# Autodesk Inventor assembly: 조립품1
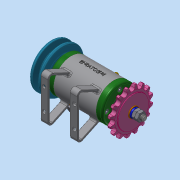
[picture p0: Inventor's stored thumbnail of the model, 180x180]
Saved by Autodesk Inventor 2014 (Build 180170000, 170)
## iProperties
Created: 2021-12
Part Number: 조립품1
Document SubType Name: Assembly
Designer: dg
Author: dg
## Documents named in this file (16)
- C:\Users\dg\Desktop\711206V1016\조립품1.iam
- C:\Users\dg\Desktop\711206V1016\본체.ipt
- C:\Users\dg\Desktop\711206V1016\V벨트풀리.ipt
- C:\Users\dg\Desktop\711206V1016\너트 M8.ipt
- C:\Users\dg\Desktop\711206V1016\니플 M6 x 0.75.ipt
- C:\Users\dg\Desktop\711206V1016\베어링 6002.ipt
- C:\Users\dg\Desktop\711206V1016\볼트 M4 x 12.ipt
- C:\Users\dg\Desktop\711206V1016\볼트 M6 x 8.ipt
- C:\Users\dg\Desktop\711206V1016\스프로킷.ipt
- C:\Users\dg\Desktop\711206V1016\스프링와셔 8.ipt
- C:\Users\dg\Desktop\711206V1016\오일 실 15 x 25 x 7.ipt
- C:\Users\dg\Desktop\711206V1016\와셔 6 x 11.5.ipt
- C:\Users\dg\Desktop\711206V1016\와셔 8 x 17.ipt
- C:\Users\dg\Desktop\711206V1016\축.ipt
- C:\Users\dg\Desktop\711206V1016\커버.ipt
- C:\Users\dg\Desktop\711206V1016\키 3 x 3.ipt
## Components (11 placed, 3 different names)
1. V벨트풀리:1
2. KS B 2023 6002 - 15 x 32 x 9:1
3. ISO 4762 M4 x 12:1
4. ISO 4762 M4 x 12:2
5. ISO 4762 M4 x 12:3
6. ISO 4762 M4 x 12:4
7. ISO 4762 M4 x 12:5
8. ISO 4762 M4 x 12:6
9. ISO 4762 M4 x 12:7
10. ISO 4762 M4 x 12:8
11. KS B 2023 6002 - 15 x 32 x 9:2
